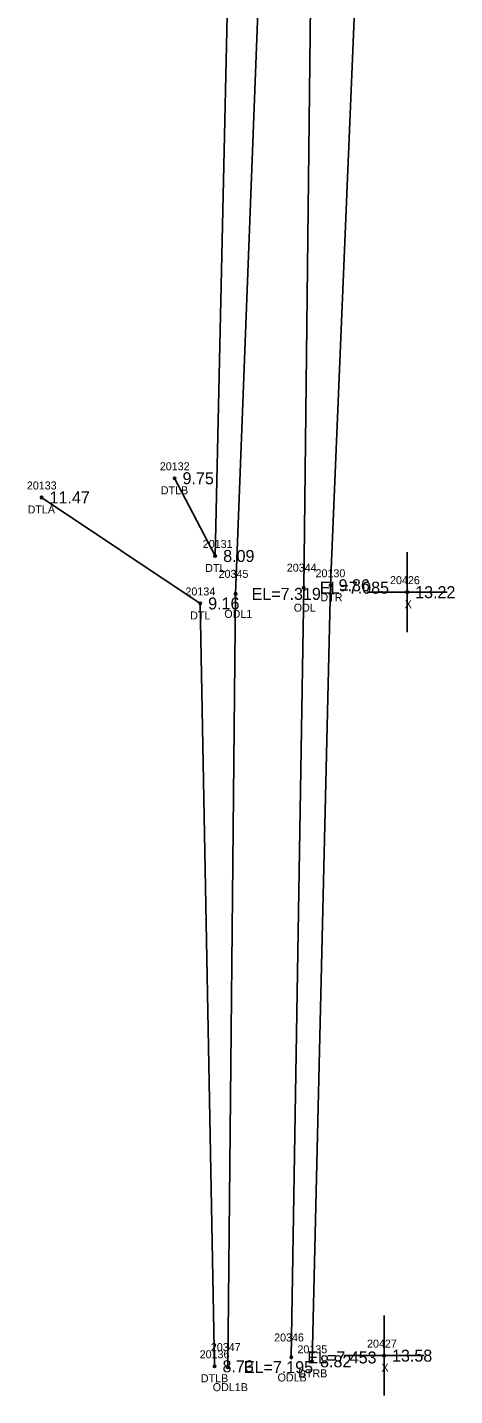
# Model space of a CAD drawing. Extents: x 2072302 to 2072980, y 127650 to 129736.
# Drawn here: x 2072378.8 to 2072432.2, y 129052.1 to 129223 of the extents above; entities that cross this region are included whole.
import ezdxf

# ---------------------------------------------------------------- set-up
doc = ezdxf.new("R2010")
doc.units = 0
for name, color, linetype in [('RD_EX_H2O', 7, 'Continuous'), ('RD_EX_H2O_txCode', 7, 'Continuous'), ('RD_EX_Misc', 7, 'Continuous'), ('RD_EX_Misc_txCode', 7, 'Continuous'), ('RD_EX_TX_H2O_ELEV', 7, 'Continuous'), ('RD_EX_TX_Misc_ELEV', 7, 'Continuous'), ('RD_SMD_Locator', 7, 'Continuous')]:
    doc.layers.add(name, color=color, linetype=linetype)

msp = doc.modelspace()

# ---------------------------------------------------------------- linework, layer by layer
at = {"layer": 'RD_EX_H2O'}
for points in [[(2072417.26, 129474.92), (2072421.43, 129368.24), (2072414.98, 129295), (2072413.35, 129153), (2072411.79, 129056.82)], [(2072430.99, 129475.23), (2072426.01, 129368.3), (2072422.66, 129295.95), (2072416.7, 129153.3), (2072414.39, 129056.34)], [(2072405.39, 129473.9), (2072401.06, 129369.87), (2072405.35, 129295.82), (2072402.29, 129156.96), (2072397.22, 129166.67)], [(2072410.97, 129474.07), (2072411.5, 129368.59), (2072410.34, 129295.43), (2072404.84, 129152.23), (2072403.87, 129055.61)], [(2072380.62, 129164.27), (2072400.42, 129151.03), (2072402.21, 129055.72)]]:
    msp.add_lwpolyline(points, dxfattribs=at)
at = {"layer": 'RD_EX_Misc'}
for p, q in [((2072426.26, 129147.44), (2072426.26, 129157.44)), ((2072421.26, 129152.44), (2072431.26, 129152.44)), ((2072423.37, 129052.05), (2072423.37, 129062.05)), ((2072418.37, 129057.05), (2072428.37, 129057.05))]:
    msp.add_line(p, q, dxfattribs=at)
at = {"layer": 'RD_SMD_Locator'}
for centre in [(2072397.22, 129166.67), (2072380.62, 129164.27), (2072402.29, 129156.96), (2072413.35, 129153), (2072416.7, 129153.3), (2072404.84, 129152.23), (2072426.26, 129152.44), (2072400.42, 129151.03), (2072402.21, 129055.72), (2072403.87, 129055.61), (2072411.79, 129056.82), (2072414.39, 129056.34), (2072423.37, 129057.05)]:
    msp.add_circle(centre, 0.15, dxfattribs=at)

# ---------------------------------------------------------------- texts
at = {"layer": 'RD_EX_H2O_txCode'}
for s, p in [('20132', (2072395.38, 129167.67)), ('20133', (2072378.78, 129165.27)), ('DTLB', (2072395.5, 129164.67)), ('DTLA', (2072378.88, 129162.27)), ('20131', (2072400.74, 129157.96)), ('DTL', (2072401.05, 129154.96)), ('20345', (2072402.72, 129154.23)), ('20344', (2072411.23, 129155)), ('20130', (2072414.82, 129154.3)), ('20134', (2072398.58, 129152.03)), ('DTR', (2072415.43, 129151.3)), ('DTL', (2072399.17, 129149.03)), ('ODL1', (2072403.43, 129149.23)), ('ODL', (2072412.1, 129150)), ('20346', (2072409.65, 129058.82)), ('20136', (2072400.36, 129056.72)), ('20347', (2072401.75, 129057.61)), ('20135', (2072412.56, 129057.34)), ('DTLB', (2072400.5, 129053.72)), ('ODLB', (2072410.08, 129053.82)), ('DTRB', (2072412.65, 129054.34)), ('ODL1B', (2072401.99, 129052.61))]:
    msp.add_text(s, height=1, dxfattribs=at).set_placement(p)
at = {"layer": 'RD_EX_Misc_txCode'}
for s, p in [('20426', (2072424.12, 129153.44)), ('X', (2072425.95, 129150.44)), ('20427', (2072421.25, 129058.05)), ('X', (2072423.05, 129055.05))]:
    msp.add_text(s, height=1, dxfattribs=at).set_placement(p)
at = {"layer": 'RD_EX_TX_H2O_ELEV'}
for s, p in [('9.75', (2072398.22, 129165.92)), ('11.47', (2072381.62, 129163.52)), ('8.09', (2072403.29, 129156.21)), ('EL=7.085', (2072415.35, 129152.25)), ('9.86', (2072417.7, 129152.55)), ('9.16', (2072401.42, 129150.28)), ('EL=7.319', (2072406.84, 129151.48)), ('EL=7.453', (2072413.79, 129056.07)), ('8.73', (2072403.21, 129054.97)), ('EL=7.195', (2072405.87, 129054.86)), ('8.82', (2072415.39, 129055.59))]:
    msp.add_text(s, height=1.5, dxfattribs=at).set_placement(p)
at = {"layer": 'RD_EX_TX_Misc_ELEV'}
for s, p in [('13.22', (2072427.26, 129151.69)), ('13.58', (2072424.37, 129056.3))]:
    msp.add_text(s, height=1.5, dxfattribs=at).set_placement(p)

doc.saveas('drawing.dxf')
